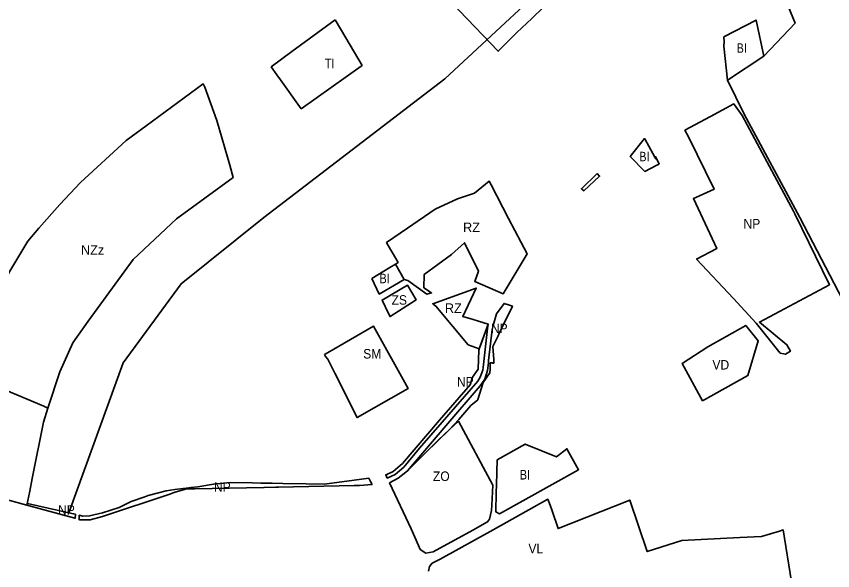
# Model space of a CAD drawing. Extents: x -650276 to -642489, y -1074311 to -1066658.
# Drawn here: x -647227 to -646196, y -1073124 to -1072424 of the extents above; entities that cross this region are included whole.
import ezdxf

# ---------------------------------------------------------------- set-up
doc = ezdxf.new("R2010")
doc.units = 0
doc.header["$LTSCALE"] = 4.8
for name, color, linetype, lineweight in [('18', 7, 'Continuous', 35), ('2', 7, 'Continuous', 35), ('30', 7, 'Continuous', 35), ('34', 7, 'Continuous', 35), ('35', 7, 'Continuous', 35), ('41', 7, 'Continuous', 35), ('42', 7, 'Continuous', 35), ('46', 7, 'Continuous', 35), ('48', 7, 'Continuous', 35), ('54', 7, 'Continuous', 35), ('6', 7, 'Continuous', 35)]:
    doc.layers.add(name, color=color, linetype=linetype, lineweight=lineweight)
doc.layers.add('62', color=7, linetype='Continuous')

msp = doc.modelspace()

# ---------------------------------------------------------------- linework, layer by layer
at = {"layer": '18'}
msp.add_lwpolyline([(-646837.81, -1072851.3), (-646836.5, -1072853.76), (-646833.67, -1072857.15), (-646824.89, -1072874.66), (-646796.68, -1072930.92), (-646732.28, -1072894.29), (-646775.85, -1072815.39), (-646834.08, -1072849.15)], close=True, dxfattribs=at)
at = {"layer": '2'}
msp.add_line((-646417.787, -1072612.168), (-646414.77, -1072610.61), dxfattribs=at)
for points in [[(-646333.34, -1072461.67), (-646328.45, -1072504.81), (-646282.47, -1072474.34), (-646292.44, -1072428.89), (-646333.33, -1072450.12), (-646332.68, -1072456.19)], [(-646778.2, -1072755.19), (-646755.1, -1072741.28), (-646748.3, -1072737.01), (-646737.05, -1072756.4), (-646768.74, -1072774.78)], [(-646620.38, -1073015.9), (-646620.71, -1073025.49), (-646621.44, -1073049.79), (-646616.55, -1073052.21), (-646516.7, -1072996.65), (-646531.46, -1072970.12), (-646544.68, -1072980.62), (-646584.23, -1072964.22), (-646619.48, -1072984.34)]]:
    msp.add_lwpolyline(points, close=True, dxfattribs=at)
for points in [[(-646420.36, -1072601.78), (-646427.95, -1072588.07), (-646432.57, -1072579.75), (-646433.36, -1072578.45), (-646451.458, -1072601.008), (-646433.024, -1072620.04), (-646417.787, -1072612.168)], [(-646414.77, -1072610.61), (-646419.11, -1072602.03), (-646419.47, -1072601.31), (-646419.02, -1072604.18), (-646420.36, -1072601.78)]]:
    msp.add_lwpolyline(points, dxfattribs=at)
at = {"layer": '30'}
for points in [[(-646824.42, -1072428.58), (-646878.91, -1072468.54), (-646905.18, -1072487.8)], [(-646867.283, -1072540.984), (-646791.569, -1072487.198), (-646790.354, -1072486.136), (-646810.77, -1072451.09), (-646824.42, -1072428.58)], [(-646905.18, -1072487.8), (-646898.1, -1072498.02), (-646893.64, -1072504.45), (-646867.283, -1072540.984)]]:
    msp.add_lwpolyline(points, dxfattribs=at)
at = {"layer": '34'}
msp.add_lwpolyline([(-646247.76, -1073138.19), (-646258.14, -1073072.71), (-646262.94, -1073074.15), (-646285.77, -1073081.01), (-646312.87, -1073082.4), (-646386.27, -1073086.15), (-646430.02, -1073100.1), (-646452.08, -1073034.96), (-646542.62, -1073071.1), (-646550.01, -1073048.55), (-646552.79, -1073041.53), (-646555.79, -1073033.92), (-646624.69, -1073072.66), (-646691.76, -1073109.71), (-646701.78, -1073114.9), (-646704.98, -1073119), (-646706.23, -1073125.02)], dxfattribs=at)
at = {"layer": '35'}
msp.add_lwpolyline([(-646360.22, -1072909.57), (-646303.02, -1072877.74), (-646289.63, -1072834.04), (-646305.56, -1072814.43), (-646353.25, -1072841.63), (-646385.86, -1072862.59)], close=True, dxfattribs=at)
at = {"layer": '41'}
msp.add_lwpolyline([(-646756.92, -1072799.26), (-646754.96, -1072803.29), (-646722.072, -1072782.236), (-646732.76, -1072763.81), (-646765, -1072782.52)], close=True, dxfattribs=at)
at = {"layer": '42'}
msp.add_lwpolyline([(-646696.83, -1072385.81), (-646618.158, -1072468.098), (-646594.606, -1072444.422), (-646575.792, -1072426.789), (-646504.244, -1072357.026)], dxfattribs=at)
msp.add_lwpolyline([(-646668.53, -1072935.52), (-646680.07, -1072945.74), (-646710.3, -1072975.31), (-646732.95, -1072998.07), (-646744.92, -1073007.46), (-646755.58, -1073013.43), (-646728.25, -1073071.54), (-646719.09, -1073092.43), (-646716.98, -1073097.26), (-646709.88, -1073101.87), (-646700.42, -1073100.42), (-646650.54, -1073072.96), (-646631.82, -1073062.65), (-646629.15, -1073059.18), (-646626.91, -1073048.17), (-646626.55, -1073041.48), (-646625.01, -1073016.38)], close=True, dxfattribs=at)
at = {"layer": '46'}
msp.add_lwpolyline([(-647284.75, -1072877.79), (-647282.31, -1072878.82), (-647192.718, -1072916.582), (-647187.445, -1072918.804), (-647172.48, -1072872.92), (-647155.72, -1072836.46), (-647136.69, -1072808.98), (-647079.74, -1072731.1), (-647025.04, -1072679.96), (-646953.2, -1072627.45), (-646957.5, -1072612.09), (-646973.68, -1072555.68), (-646989.01, -1072513.62), (-646991.24, -1072509.24), (-647063.38, -1072562.42), (-647088.397, -1072580.865), (-647088.4, -1072580.868), (-647146.21, -1072634.02), (-647172.36, -1072661.69), (-647198.77, -1072691.71), (-647212.92, -1072708.05), (-647236.54, -1072748.09), (-647252.29, -1072783.24), (-647263.58, -1072809.97)], close=True, dxfattribs=at)
at = {"layer": '48'}
msp.add_line((-646779.55, -1073011.68), (-646781.703, -1073007.452), dxfattribs=at)
for points in [[(-646194.19, -1072404.62), (-646254.75, -1072404.25), (-646243.17, -1072432.88), (-646282.47, -1072474.34), (-646328.45, -1072504.81), (-646307.6, -1072547.74), (-646236.97, -1072678.31), (-646171.72, -1072803.51)], [(-646918.156, -1073013.511), (-646928.807, -1073013.313), (-646956.919, -1073012.775), (-646978.077, -1073014.931), (-646997.824, -1073018.092), (-647006.715, -1073019.236), (-647006.15, -1073020.99), (-647001.66, -1073020.72), (-646914.54, -1073019)], [(-646781.703, -1073007.452), (-646809.778, -1073011.019), (-646838.25, -1073014.938), (-646861.07, -1073014.672), (-646890.523, -1073014.073), (-646904.131, -1073013.793), (-646914.796, -1073013.573), (-646918.156, -1073013.511)], [(-646800.44, -1073016.74), (-646793.8, -1073016.61), (-646777.74, -1073015.29), (-646779.55, -1073011.68)], [(-646914.54, -1073019), (-646913.94, -1073018.99), (-646899.22, -1073018.7), (-646895.76, -1073018.63), (-646800.44, -1073016.74)]]:
    msp.add_lwpolyline(points, dxfattribs=at)
for points in [[(-646310.01, -1072549.22), (-646319.56, -1072536.05), (-646320.62, -1072534.6), (-646350.18, -1072550.59), (-646382.41, -1072568.01), (-646377.84, -1072576.29), (-646345.6, -1072642.55), (-646368.51, -1072652.81), (-646371.66, -1072654.2), (-646342.08, -1072717.43), (-646367.72, -1072730.68), (-646321.171, -1072780.535), (-646292.17, -1072811.6), (-646261.97, -1072849.66), (-646255.39, -1072850.83), (-646249.04, -1072847.16), (-646253.56, -1072838.8), (-646288.27, -1072810.22), (-646199.72, -1072763.1), (-646243.32, -1072673.57), (-646245.13, -1072670.2), (-646278.44, -1072608.07)], [(-646493.229, -1072622.74), (-646513.209, -1072641.935), (-646510.28, -1072644.42), (-646490.11, -1072626.15)], [(-646644.059, -1072908.208), (-646637.2, -1072886.57), (-646628.7, -1072874.5), (-646628.58, -1072869.88), (-646628.36, -1072861.71), (-646627.159, -1072861.792), (-646625.96, -1072861.874), (-646625.3, -1072861.919), (-646624.824, -1072861.951), (-646623.67, -1072862.024), (-646623.712, -1072861.37), (-646623.95, -1072857.6), (-646625.02, -1072841.21), (-646618.521, -1072827.719), (-646617.407, -1072825.407), (-646614.07, -1072818.47), (-646600.37, -1072790.04), (-646603.99, -1072788.901), (-646610.86, -1072786.74), (-646620.27, -1072799.95), (-646624.54, -1072814.52), (-646625.91, -1072819.66), (-646630.45, -1072858.93), (-646630.57, -1072859.99), (-646630.76, -1072861.61), (-646631.89, -1072871.33), (-646635.11, -1072882.47), (-646640.96, -1072890.83), (-646684.36, -1072941.43), (-646732.95, -1072998.07), (-646710.3, -1072975.31), (-646693.9, -1072958.84), (-646680.07, -1072945.74), (-646668.09, -1072933.43), (-646652.76, -1072915.66), (-646644.069, -1072908.218), (-646644.061, -1072908.209)], [(-646642.438, -1072844.29), (-646642.939, -1072845.68), (-646643.574, -1072869.57), (-646650.798, -1072879.828), (-646653.846, -1072889.44), (-646692.432, -1072934.135), (-646739.241, -1072988.798), (-646751.061, -1072999.106), (-646758.883, -1073002.885), (-646760.416, -1073003.25), (-646758.44, -1073007.19), (-646748.51, -1073002.74), (-646737.7, -1072993.52), (-646717.7, -1072969.5), (-646689.13, -1072936.62), (-646644.12, -1072884.84), (-646640.92, -1072879.6), (-646637.92, -1072870.91), (-646637.52, -1072867.43), (-646631.85, -1072818.45), (-646631.08, -1072812.68), (-646640.313, -1072838.394), (-646642.404, -1072844.195), (-646642.39, -1072844.2)], [(-647293.317, -1072873.549), (-647293.351, -1072873.533), (-647331.82, -1072854.49), (-647375.92, -1072833.99), (-647387.64, -1072868.69), (-647392.96, -1072918.277), (-647394.87, -1072936.08), (-647388.62, -1072948.03), (-647395.47, -1072993.25), (-647367.45, -1073002.47), (-647353.78, -1073003.1), (-647213.99, -1073041.449), (-647210.396, -1073023.593), (-647207.176, -1073007.598), (-647192.93, -1072936.82), (-647187.445, -1072918.804), (-647192.718, -1072916.582), (-647282.31, -1072878.82), (-647284.75, -1072877.79)], [(-647006.715, -1073019.236), (-647009.402, -1073019.582), (-647026.763, -1073021.811), (-647037.971, -1073023.24), (-647060.677, -1073029.351), (-647064.784, -1073030.747), (-647082.267, -1073036.684), (-647097.466, -1073044.268), (-647118.513, -1073051.327), (-647134.596, -1073054.974), (-647143.312, -1073055.421), (-647147.85, -1073054.204), (-647147.91, -1073059.64), (-647147.43, -1073059.78), (-647147.17, -1073059.97), (-647134.03, -1073059.94), (-647118.27, -1073055.88), (-647033.44, -1073027.43), (-647028.91, -1073025.91), (-647026.54, -1073025.11), (-647013.4, -1073021.42), (-647006.15, -1073020.99)], [(-647152.621, -1073052.925), (-647154.999, -1073052.287), (-647161.068, -1073050.946), (-647161.068, -1073050.946), (-647161.068, -1073050.946), (-647213.218, -1073039.42), (-647213.562, -1073039.322), (-647213.99, -1073041.449), (-647153.44, -1073058.06), (-647152.96, -1073058.19)]]:
    msp.add_lwpolyline(points, close=True, dxfattribs=at)
at = {"layer": '54'}
msp.add_lwpolyline([(-646516, -1072345), (-646685.823, -1072502.987), (-646914.429, -1072678.004), (-647018.969, -1072761.795), (-647092.194, -1072861.614), (-647161.068, -1073050.946)], dxfattribs=at)
at = {"layer": '6'}
for points in [[(-646737.05, -1072756.4), (-646732.5, -1072757.63), (-646708.65, -1072775.02), (-646702.45, -1072773.39), (-646712.46, -1072766.76), (-646711.79, -1072750.02), (-646677.39, -1072724.85), (-646660.89, -1072709.97), (-646643.36, -1072746.04), (-646647.93, -1072759.01), (-646612.11, -1072774.56), (-646581.92, -1072723.91), (-646589.37, -1072709.83), (-646605.23, -1072679.37), (-646627.32, -1072636.95), (-646629.86, -1072632.07), (-646648.27, -1072647.48), (-646669.6, -1072654.53), (-646697.89, -1072667.65)], [(-646697.89, -1072667.65), (-646732.95, -1072691.68), (-646759.491, -1072709.878), (-646757.5, -1072713.3), (-646747.87, -1072729.85), (-646744.94, -1072734.88), (-646748.3, -1072737.01), (-646737.05, -1072756.4)], [(-646653.02, -1072806.07), (-646663.07, -1072803.04), (-646663.07, -1072803.04), (-646646.12, -1072767.32), (-646646.31, -1072767.388), (-646701.12, -1072787.08), (-646697.09, -1072790.03), (-646656.36, -1072839.08)], [(-646656.36, -1072839.08), (-646642.404, -1072844.195), (-646631.08, -1072812.68), (-646643.01, -1072809.08), (-646651.11, -1072806.64), (-646653.02, -1072806.07)]]:
    msp.add_lwpolyline(points, dxfattribs=at)

# ---------------------------------------------------------------- texts
at = {"layer": '62'}
for s, width, p in [('BI', 0.85, (-646317, -1072470.167)), ('TI', 0.85, (-646837.377, -1072489.619)), ('BI', 0.85, (-646440, -1072607.167)), ('NP', 0.95, (-646308.335, -1072692.048)), ('BI', 0.85, (-646768.325, -1072761.133)), ('ZS', 0.95, (-646753.085, -1072788.28)), ('NP', 0.95, (-646627.575, -1072824.064)), ('SM', 0.95, (-646788.938, -1072856.245)), ('VD', 0.95, (-646347.605, -1072870.155)), ('NP', 0.95, (-646670.505, -1072891.594)), ('ZO', 0.95, (-646700.791, -1073010.902)), ('BI', 0.85, (-646590.991, -1073009.043)), ('NP', 0.95, (-646977.505, -1073024.594)), ('NP', 0.95, (-647174.505, -1073053.594)), ('VL', 0.95, (-646580.107, -1073102.218))]:
    msp.add_text(s, height=12, dxfattribs=dict(at, width=width)).set_placement(p)
for s, p in [('RZ', (-646662.725, -1072696.633)), ('NZz', (-647145.58, -1072725.109)), ('RZ', (-646685.725, -1072798.633))]:
    msp.add_text(s, height=12, dxfattribs=at).set_placement(p)

doc.saveas('drawing.dxf')
